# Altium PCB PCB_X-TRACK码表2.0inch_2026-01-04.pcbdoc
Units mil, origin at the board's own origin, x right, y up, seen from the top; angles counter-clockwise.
Board outline 4520 x 5405.38 mil, 2 copper layers (Top Layer, Bottom Layer); 72 components, 59 nets, 273 pads, 238 vias.
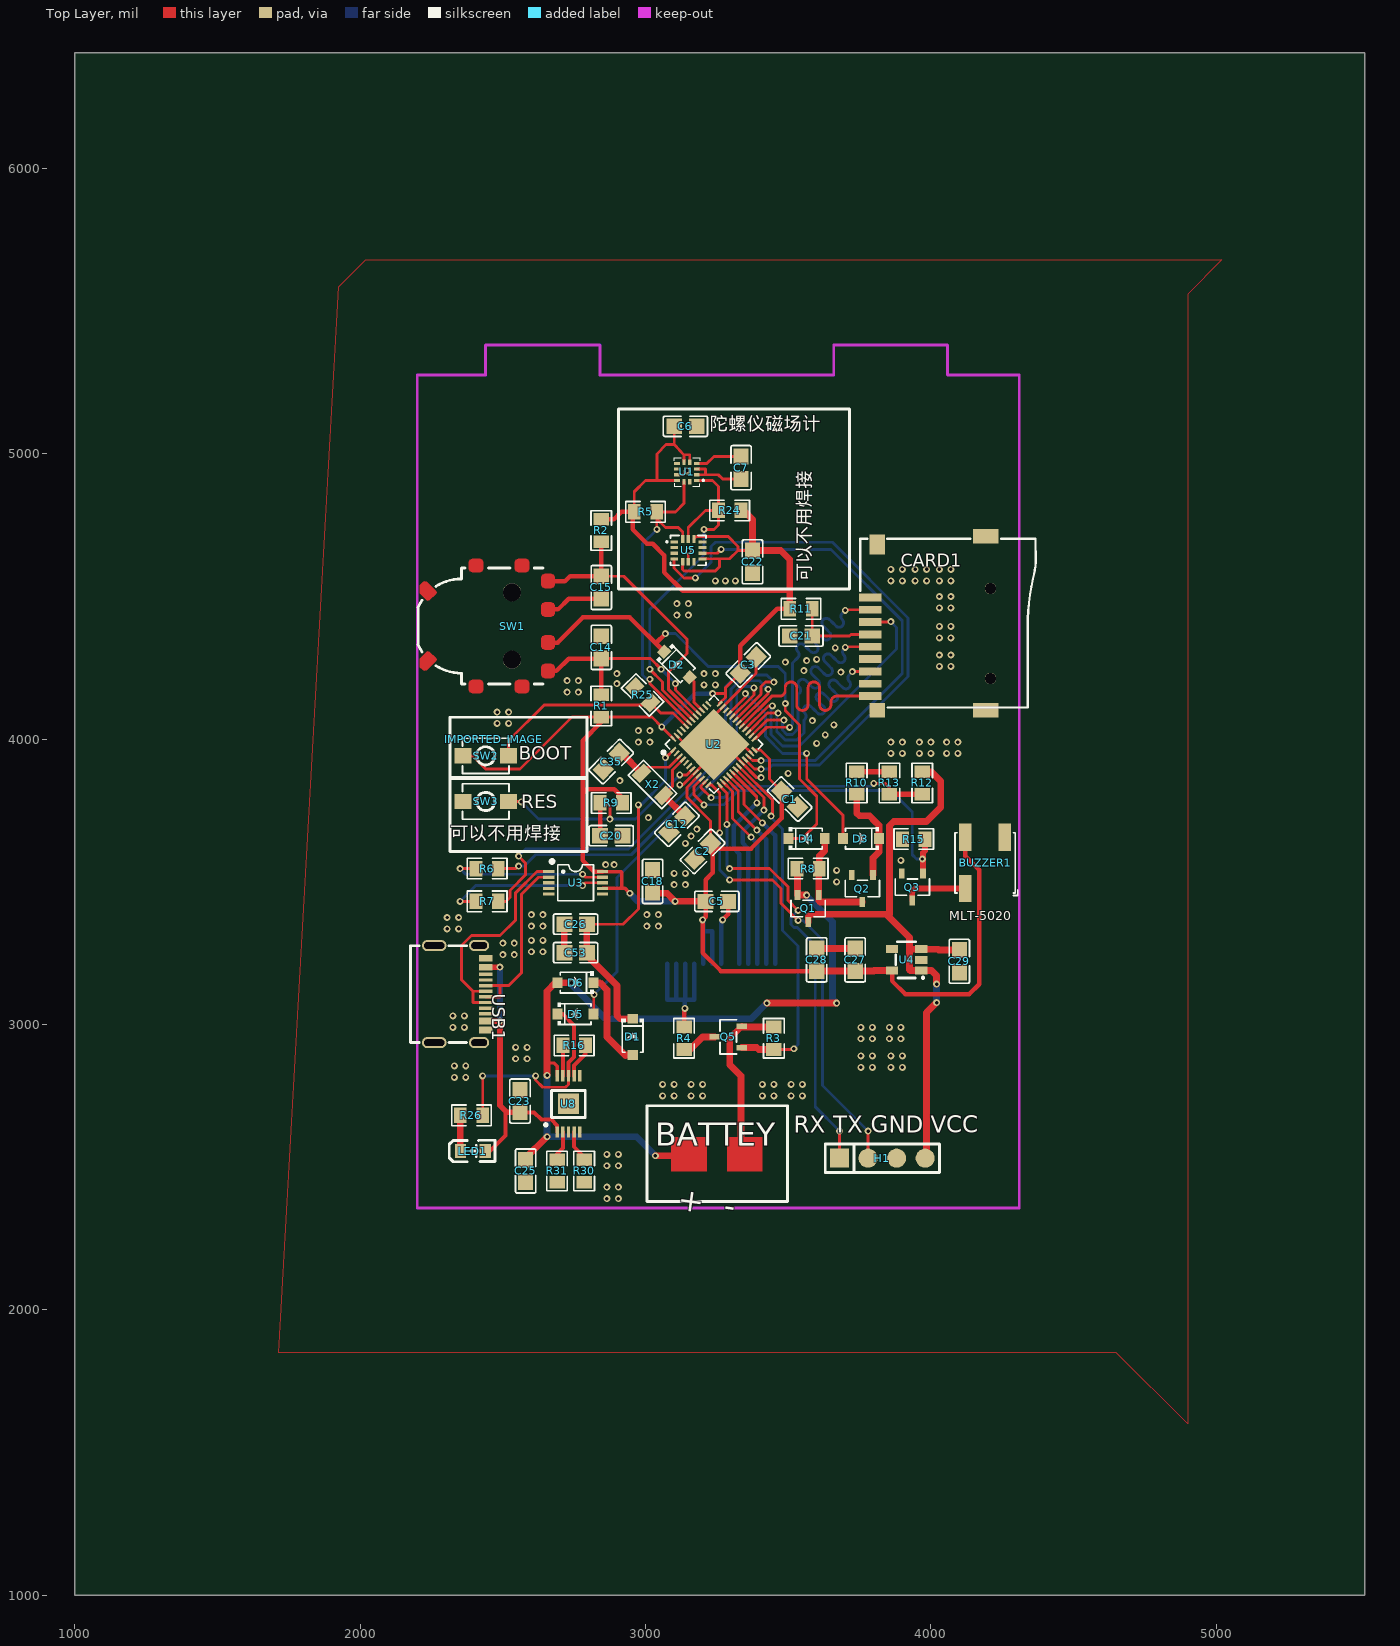
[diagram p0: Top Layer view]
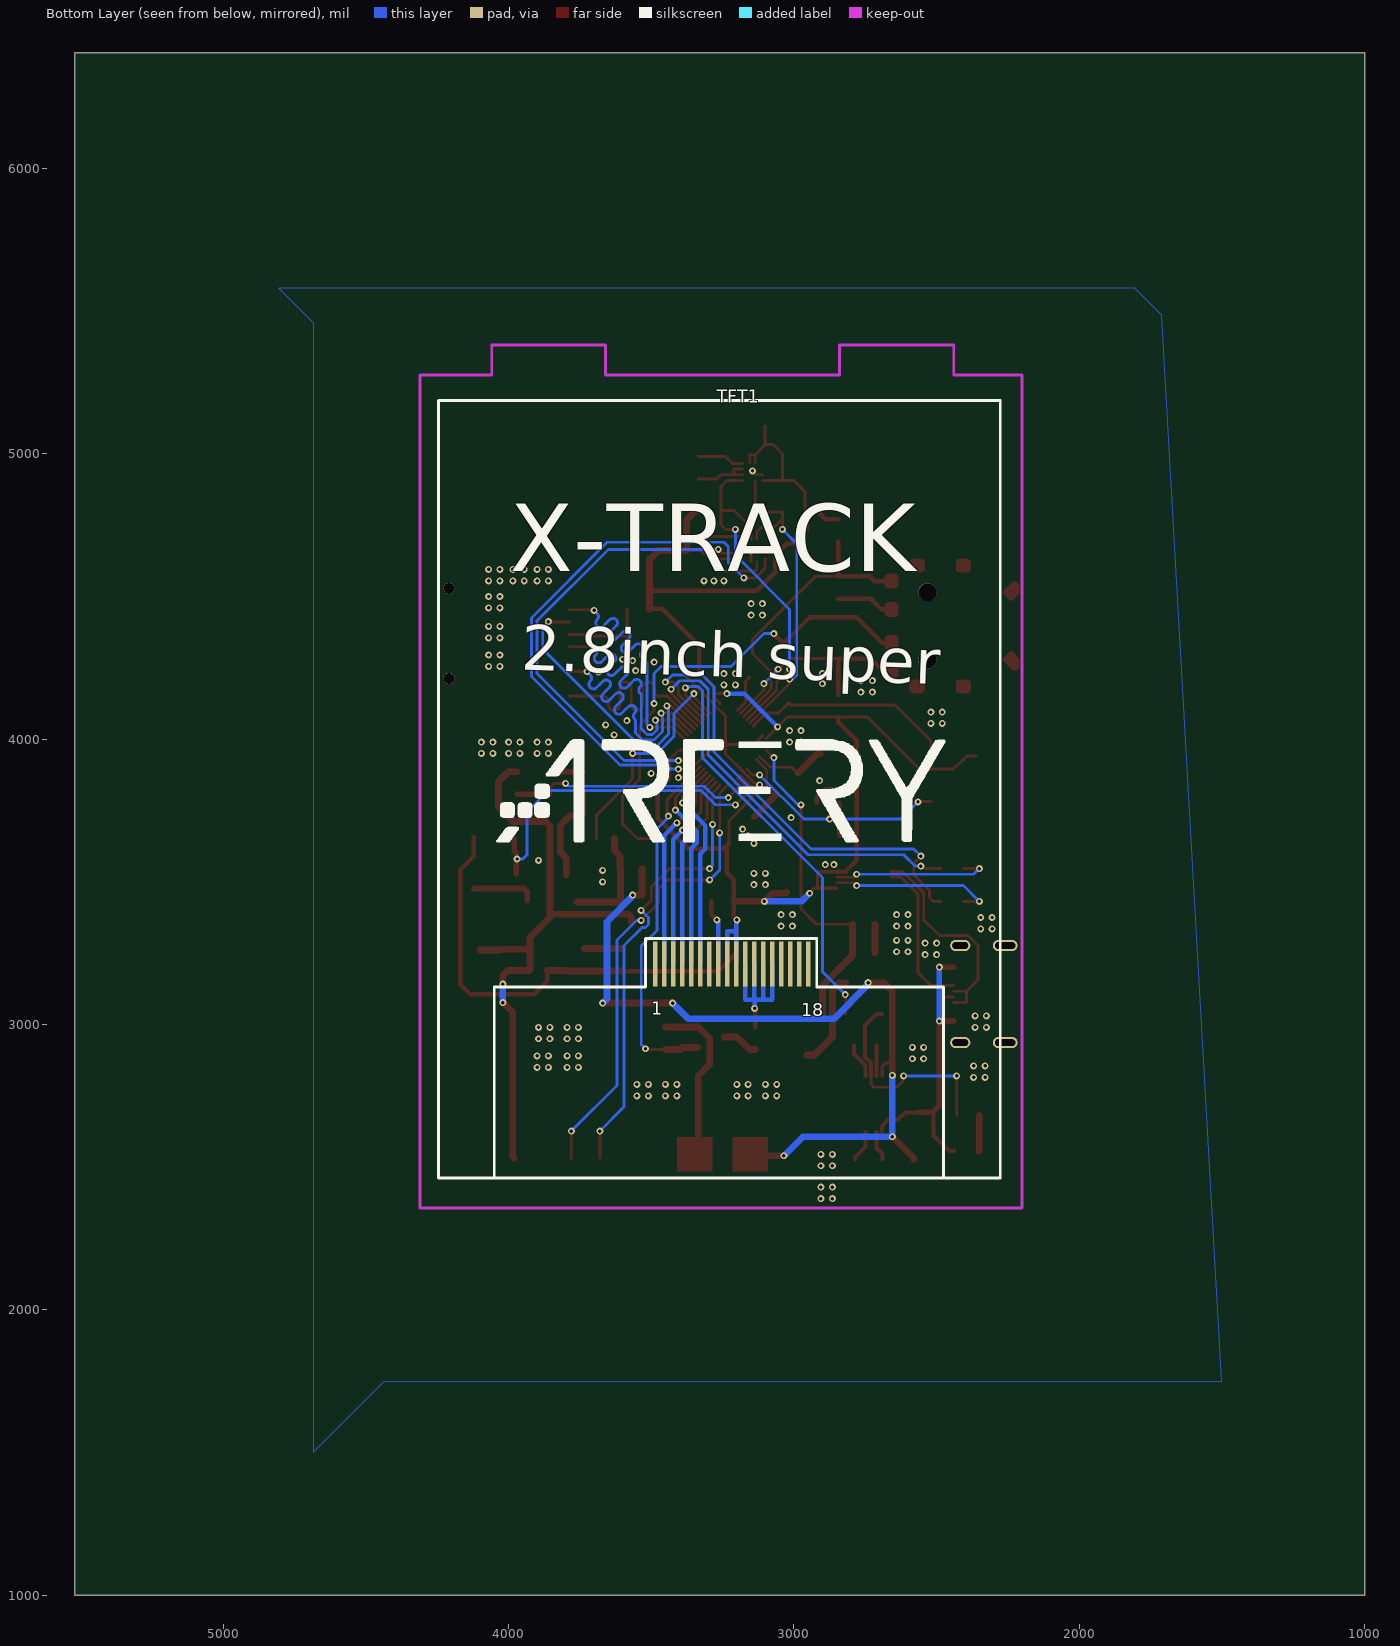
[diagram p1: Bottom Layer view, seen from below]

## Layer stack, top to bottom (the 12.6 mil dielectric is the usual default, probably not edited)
Top Layer: signal copper (thickness not stored)
Dielectric: dielectric 12.6, FR-4, Dk 4.8
Bottom Layer: signal copper (thickness not stored)

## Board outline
5520,1000 1000,1000 1000,6405.38 5520,6405.38

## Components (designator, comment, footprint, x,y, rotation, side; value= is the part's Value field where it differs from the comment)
BUZZER1 "MLT-5020" BUZ-SMD_3P-L5.2-W5.2-P3.50-BR 4190.01,3566.58 r0 top
C1 "100nF" C0805 3505,3790 r135 top
C2 "100nF" C0805 3200.01,3606.58 r45 top
C3 "100nF" C0805 3360,4260 r225 top
C5 "10uF" C0805 3250.01,3431.58 r0 top
C6 "100nF" C0805 3140.01,5096.58 r0 top
C7 "100nF" C0805 3335.01,4951.58 r270 top
C12 "9pF" C0805 3110.01,3701.58 r45 top
C14 "100nF" C0805 2845.01,4321.58 r270 top
C15 "100nF" C0805 2845.01,4531.58 r90 top
C18 "100nF" C0805 3025.01,3501.58 r90 top
C20 "100nF" C0805 2880.01,3661.58 r0 top
C21 "1uF" C0805 3545.01,4361.58 r180 top
C22 "100nF" C0805 3375.01,4621.58 r270 top
C23 "10uF" C0805 2560.01,2731.58 r270 top
C25 "10uF" C0805 2580.01,2486.58 r90 top
C26 "10uF" C0805 2755.01,3351.58 r0 top
C27 "10uF" C0805 3735.01,3226.58 r90 top
C28 "10uF" C0805 3600.01,3226.58 r90 top
C29 "10uF" C0805 4100.01,3221.58 r270 top
C35 "9pF" C0805 2880.01,3921.58 r45 top
C53 "100nF" C0805 2755.01,3251.58 r180 top
CARD1 "TF卡插座-TF-015" TF卡插座-TF-015 3990.01,4406.58 r90 top
D1 "1N4148W_C7420318" SOD-123_L2.7-W1.6-LS3.7-FD 2955.01,2956.58 r90 top
D2 "1N4148W_C7420318" SOD-123_L2.7-W1.6-LS3.7-FD 3110.01,4261.58 r135 top
D3 "1N4148W_C7420318" SOD-123_L2.7-W1.6-LS3.7-FD 3755.01,3651.58 r0 top
D4 "1N4148W_C7420318" SOD-123_L2.7-W1.6-LS3.7-FD 3565.01,3651.58 r180 top
D5 "1N4148W_C7420318" SOD-123_L2.7-W1.6-LS3.7-FD 2755.01,3036.58 r180 top
D6 "1N4148W_C7420318" SOD-123_L2.7-W1.6-LS3.7-FD 2755.01,3146.58 r0 top
H1 "Z-211-0411-0021-001" HDR-TH_4P-P2.54-V-M 3830.01,2531.58 r0 top
IMPORTED_IMAGE "IMPORTED_IMAGE" IMPORTED_IMAGE 2468.91,4000.51 r0 top
LED1 "XL-2012SURC" LED0805-RD_RED 2395.01,2556.58 r0 top
Q1 "SI2305" SOT-23-3_L2.9-W1.3-P1.90-LS2.4-BR 3570.01,3406.58 r90 top
Q2 "SI2302" SOT-23-3_L2.9-W1.3-P1.90-LS2.4-BR 3760.01,3476.58 r90 top
Q3 "SI2302" SOT-23-3_L2.9-W1.3-P1.90-LS2.4-BR 3935.01,3481.58 r90 top
Q5 "SI2302" SOT-23-3_L2.9-W1.3-P1.90-LS2.4-BR 3290.01,2956.58 r0 top
R1 "10K" R0805 2845.01,4116.58 r270 top
R2 "10K" R0805 2845.01,4731.58 r270 top
R3 "10K" R0805 3450.01,2951.58 r90 top
R4 "4R7" R0805 3135.01,2951.58 r270 top
R5 "10K" R0805 3000.01,4796.58 r0 top
R6 "100" R0805 2445.01,3546.58 r0 top
R7 "100" R0805 2445.01,3431.58 r180 top
R8 "20k" R0805 3570.01,3546.58 r0 top
R9 "10K" R0805 2880.01,3776.58 r180 top
R10 "20k" R0805 3740.01,3846.58 r270 top
R11 "4R7" R0805 3545.01,4456.58 r0 top
R12 "20k" R0805 3970.01,3846.58 r90 top
R13 "20k" R0805 3855.01,3846.58 r270 top
R15 "10K" R0805 3940,3650 r0 top
R16 "10K" R0805 2750.01,2926.58 r0 top
R24 "10K" R0805 3295.01,4801.58 r180 top
R25 "10K" R0805 2990,4155 r135 top
R26 "2.2K" R0805 2390.01,2681.58 r0 top
R30 "2k" R0805 2785.01,2486.58 r90 top
R31 "1k" R0805 2690.01,2486.58 r90 top
SW1 "TSIQ-02FVS3" 贴片旋转编码开关_TSIQ-02FVS3 2355.01,4396.58 r90 top
SW2 "3×4×2.5_2脚小龟" SW-SMD_L4.0-W2.9-LS5.0 2440.01,3941.58 r180 top
SW3 "3×4×2.5_2脚小龟" SW-SMD_L4.0-W2.9-LS5.0 2440.01,3781.58 r0 top
TFT1 "2.8寸TFT 18PIN*0.8 焊接  240*320" "2.8寸TFT SPI,18PIN 0.8MM 240*320" 3220.01,3401.58 r0 bottom
U1 "LIS3MDLTR" LGA-12_L2.0-W2.0-P0.50-BL 3145.01,4936.58 r90 top
U2 "AT32F403ACGU7" QFN-48_L6.0-W6.0-P0.40-BL-EP4.2 3240.01,3981.58 r45 top
U3 "CH340E" MSOP-10_L3.0-W3.0-P0.50-LS5.0-BL 2755.01,3496.58 r270 top
U4 "ME6230C33M5G" TSOT-23-5_L2.9-W1.6-P0.95-LS2.8-BR 3915.01,3226.58 r0 top
U5 "LSM6DSMTR" LGA-14_L3.0-W2.5-P0.50-TL 3150.01,4661.58 r0 top
U8 "BQ24092DGQT" HVSSOP-10_L3.0-W3.0-P0.50-LS4.9-BL-EP 2730.01,2721.58 r0 top
USB1 "GT-USB-7010B" USB-C-SMD_GT-USB-7010B 2350.01,3106.58 r270 top
X2 "32.768KHz" OSC-SMD_2P-L3.2-W1.5 3025.01,3841.58 r315 top
? "" ? 3260.01,5757.48 r0 top
? "" ? 4793.21,3876.89 r0 top
? "" ? 2400.58,3824.38 r0 top
? "" ? 3260.76,5059.93 r0 top

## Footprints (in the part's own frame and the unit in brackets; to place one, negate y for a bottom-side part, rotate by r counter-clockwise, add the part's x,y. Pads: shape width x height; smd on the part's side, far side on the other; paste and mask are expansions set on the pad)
"2.8寸TFT SPI,18PIN 0.8MM 240*320" [mil]
BUZ-SMD_3P-L5.2-W5.2-P3.50-BR [mm]
  rect 1.12x2.425 smd paste+0 mask+0.051: 1(1.75,2.287) 2(-1.75,2.287) 3(-1.75,-2.288)
  silkscreen extent -2.68,-2.9 2.9,2.68
C0805 [mm]
  rect 1.41x1.35 smd paste-100 mask+0.051: 1(-1,0) 2(1,0)
  silkscreen extent -1.96,-0.9 1.96,0.9
HDR-TH_4P-P2.54-V-M [mm]
  rect 1.7x1.7 smd paste+0 mask+0.051: 1(-3.81,0)
  round 1.7 smd paste+0 mask+0.051: 2(-1.27,0) 3(1.27,0) 4(3.81,0)
  silkscreen extent -5.08,-1.27 5.08,1.27
HVSSOP-10_L3.0-W3.0-P0.50-LS4.9-BL-EP [mm]
  rect 0.3x1 smd paste+0 mask+0.051: 1(-1,-2.5) 2(-0.5,-2.5) 3(0,-2.5) 4(0.5,-2.5) 5(1,-2.5) 6(1,2.5) 7(0.5,2.5) 8(0,2.5) 9(-0.501,2.5) 10(-1.001,2.5)
  rect 1.89x1.83 smd paste+0 mask+0.051: 11(0,0)
  silkscreen extent -2.13,-1.98 1.5,1.2
IMPORTED_IMAGE [mil]
LED0805-RD_RED [mm]
  rect 1x1.25 smd paste+0 mask+0.051: 1(-1.1,0) 2(1.1,0)
  silkscreen extent -2.1,-0.95 1.98,0.96
LGA-12_L2.0-W2.0-P0.50-BL [mm]
  rect 0.28x0.5 smd paste+0 mask+0.051: 1(-0.75,-0.875) 2(-0.25,-0.875) 3(0.25,-0.875) 4(0.75,-0.875) 7(0.75,0.875) 8(0.25,0.875) 9(-0.25,0.875) 10(-0.75,0.875)
  rect 0.5x0.28 smd paste+0 mask+0.051: 5(0.875,-0.25) 6(0.875,0.25) 11(-0.875,0.25) 12(-0.875,-0.25)
  silkscreen extent -1.27,-1.53 1.27,1.14
LGA-14_L3.0-W2.5-P0.50-TL [mm]
  rect 0.675x0.28 smd paste+0 mask+0.051: 1(-1.262,0.75) 2(-1.262,0.25) 3(-1.262,-0.25) 4(-1.262,-0.75) 8(1.262,-0.75) 9(1.262,-0.25) 10(1.262,0.25) 11(1.262,0.75)
  rect 0.28x0.675 smd paste+0 mask+0.051: 5(-0.5,-1.012) 6(0,-1.012) 7(0.5,-1.012) 12(0.5,1.012) 13(0,1.012) 14(-0.5,1.012)
  silkscreen extent -1.98,-1.33 1.58,1.33
MSOP-10_L3.0-W3.0-P0.50-LS5.0-BL [mm]
  rect 0.28x1 smd paste+0 mask+0.051: 1(-1,-2.4) 2(-0.5,-2.4) 3(0,-2.4) 4(0.5,-2.4) 5(1,-2.4) 6(1,2.4) 7(0.5,2.4) 8(0,2.4) 9(-0.5,2.4) 10(-1,2.4)
  silkscreen extent -2.05,-2.25 1.6,1.6
OSC-SMD_2P-L3.2-W1.5 [mm]
  rect 1x1.5 smd paste+0 mask+0.051: 1(-1.397,0) 2(1.397,0)
  silkscreen extent -2.1,-0.95 2.1,0.95
QFN-48_L6.0-W6.0-P0.40-BL-EP4.2 [mm]
  rect 0.665x0.2 smd paste-100 mask+0.05: 1(-2.908,2.2) 2(-2.908,1.8) 3(-2.908,1.4) 4(-2.908,1) 5(-2.908,0.6) 6(-2.908,0.2) 7(-2.908,-0.2) 8(-2.908,-0.6) 9(-2.908,-1) 10(-2.908,-1.4) 11(-2.908,-1.8) 12(-2.908,-2.2) 25(2.908,-2.2) 26(2.908,-1.8) 27(2.908,-1.4) 28(2.908,-1) 29(2.908,-0.6) 30(2.908,-0.2) 31(2.908,0.2) 32(2.908,0.6) 33(2.908,1) 34(2.908,1.4) 35(2.908,1.8) 36(2.908,2.2)
  rect 0.2x0.665 smd paste-100 mask+0.05: 13(-2.2,-2.908) 14(-1.8,-2.908) 15(-1.4,-2.908) 16(-1,-2.908) 17(-0.6,-2.908) 18(-0.2,-2.908) 19(0.2,-2.908) 20(0.6,-2.908) 21(1,-2.908) 22(1.4,-2.908) 23(1.8,-2.908) 24(2.2,-2.908) 37(2.2,2.908) 38(1.8,2.908) 39(1.4,2.908) 40(1,2.908) 41(0.6,2.908) 42(0.2,2.908) 43(-0.2,2.908) 44(-0.6,2.908) 45(-1,2.908) 46(-1.4,2.908) 47(-1.8,2.908) 48(-2.2,2.908)
  rect 4.5x4.5 smd paste-100: 49(0,0)
  silkscreen extent -3.76,-3.08 3.08,3.08
R0805 [mil]
  rect 44.59x54.21 smd paste-3937.01 mask+2: 1(-39.37,0) 2(39.37,0)
  silkscreen extent -69,-36 69,36
SOD-123_L2.7-W1.6-LS3.7-FD [mm]
  rect 0.88x0.96 smd paste+0 mask+0.051: 1(-1.61,0) 2(1.61,0)
  silkscreen extent -1.38,-1 1.6,1
SOT-23-3_L2.9-W1.3-P1.90-LS2.4-BR [mm]
  rect 0.9x0.5 smd paste+0 mask+0.051: 1(1.2,-0.95) 2(1.2,0.95) 3(-1.2,0)
  silkscreen extent -0.73,-1.53 0.73,1.53
SW-SMD_L4.0-W2.9-LS5.0 [mm]
  rect 1.53x1.36 smd paste+0 mask+0.051: 1(-2.035,0) 2(2.035,0)
  silkscreen extent -2.08,-1.58 2.08,1.58
TF卡插座-TF-015 [mm]
  rect 0.7x2 smd paste+0 mask+0.102: 1(2.292,5.145) 2(1.192,5.143) 3(0.096,5.145) 4(-1.004,5.145) 5(-2.103,5.145) 6(-3.201,5.145) 7(-4.297,5.145) 8(-5.395,5.145) 9(-6.499,5.145)
  rect 1.27x1.397 smd paste+0 mask+0.102: 10(-7.747,4.507)
  rect 1.27x2.286 smd paste+0 mask+0.102: 11(-7.747,-5.145) 12(7.747,-5.145)
  rect 1.778x1.397 smd paste+0 mask+0.102: 13(6.985,4.507)
  round 1 hole 1 unplated paste+0: ""(-4.915,-5.557) ""(3.084,-5.554)
  silkscreen extent -7.52,-9.6 7.52,6.02
TSOT-23-5_L2.9-W1.6-P0.95-LS2.8-BR [mm]
  rect 1.1x0.7 smd paste+0 mask+0.051: 1(1.294,-0.951) 2(1.294,-0.001) 3(1.294,0.951) 4(-1.294,0.951) 5(-1.294,-0.949)
  silkscreen extent -0.97,-1.65 1.52,1.61
USB-C-SMD_GT-USB-7010B [mm]
  rect 0.6x1.2 smd paste-100 mask+0.051: 1(-3.2,2.3) 2(-2.4,2.3) 11(2.4,2.3) 12(3.2,2.3)
  rect 0.3x1.2 smd paste-100 mask+0.051: 3(-1.75,2.3) 4(-1.25,2.3) 5(-0.75,2.3) 6(-0.25,2.3) 7(0.25,2.3) 8(0.75,2.3) 9(1.25,2.3) 10(1.75,2.3)
  oval 1x1.8 hole 0.6 slot 1.4 at 90 deg paste+0 mask+0.051: 13(-4.32,1.7) 14(4.32,1.7)
  oval 1x2.2 hole 0.6 slot 1.8 at 90 deg paste+0 mask+0.051: 15(-4.32,-2.3) 16(4.32,-2.3)
  silkscreen extent -4.3,-4.4 4.3,0.57
贴片旋转编码开关_TSIQ-02FVS3 [mm]
  round 1.6 hole 1.6 unplated paste+0: ""(-3,-4.5) ""(3,-4.5)
  Top Layer region: -6,-1.65 -5.912,-1.862 -5.7,-1.95 -5.1,-1.95 -4.888,-1.862 -4.8,-1.65 -4.8,-0.95 -4.888,-0.738 -5.1,-0.65 -5.7,-0.65 -5.912,-0.738 -6,-0.95
  Top Layer region: -6,-5.75 -5.912,-5.962 -5.7,-6.05 -5.1,-6.05 -4.888,-5.962 -4.8,-5.75 -4.8,-5.05 -4.888,-4.838 -5.1,-4.75 -5.7,-4.75 -5.912,-4.838 -6,-5.05
  Top Layer region: -4.65,-8 -4.562,-8.212 -4.35,-8.3 -3.65,-8.3 -3.438,-8.212 -3.35,-8 -3.35,-7.4 -3.438,-7.188 -3.65,-7.1 -4.35,-7.1 -4.562,-7.188 -4.65,-7.4
  Top Layer region: -2.125,-8 -2.037,-8.212 -1.825,-8.3 -1.125,-8.3 -0.913,-8.212 -0.825,-8 -0.825,-7.4 -0.913,-7.188 -1.125,-7.1 -1.825,-7.1 -2.037,-7.188 -2.125,-7.4
  Top Layer region: 0.825,-8 0.913,-8.212 1.125,-8.3 1.825,-8.3 2.037,-8.212 2.125,-8 2.125,-7.4 2.037,-7.188 1.825,-7.1 1.125,-7.1 0.913,-7.188 0.825,-7.4
  Top Layer region: 3.35,-8 3.438,-8.212 3.65,-8.3 4.35,-8.3 4.562,-8.212 4.65,-8 4.65,-7.4 4.562,-7.188 4.35,-7.1 3.65,-7.1 3.438,-7.188 3.35,-7.4
  Top Layer region: 4.8,-5.75 4.888,-5.962 5.1,-6.05 5.7,-6.05 5.912,-5.962 6,-5.75 6,-5.05 5.912,-4.838 5.7,-4.75 5.1,-4.75 4.888,-4.838 4.8,-5.05
  Top Layer region: 4.8,-1.65 4.888,-1.862 5.1,-1.95 5.7,-1.95 5.912,-1.862 6,-1.65 6,-0.95 5.912,-0.738 5.7,-0.65 5.1,-0.65 4.888,-0.738 4.8,-0.95
  Top Layer region: 2.3,2.85 2.25,3 2.3,3.1 2.9,3.7 3.65,3.7 3.95,3.4 4,3.25 3.95,3.1 3.1,2.25 3,2.2 2.85,2.25
  Top Layer region: -2.3,2.85 -2.25,3 -2.3,3.1 -2.9,3.7 -3.65,3.7 -3.95,3.4 -4,3.25 -3.95,3.1 -3.1,2.25 -2.95,2.2 -2.85,2.25
  silkscreen extent -5.15,-7.25 5.15,3.86
? [mil]

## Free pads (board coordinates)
  rect 15.75x157.48 smd far side paste+0 mask+3.94: 1(3485.45,3212.6) 2(3453.95,3212.6) 3(3422.45,3212.6) 4(3390.96,3212.6) 5(3359.46,3212.6) 6(3327.97,3212.6) 7(3296.47,3212.6) 8(3264.97,3212.6) 9(3233.48,3212.6) 10(3201.98,3212.6) 11(3170.49,3212.6) 12(3138.99,3212.6) 13(3107.49,3212.6) 14(3076,3212.6) 15(3044.5,3212.6) 16(3013.01,3212.6) 17(2981.51,3212.6) 18(2950.01,3212.6)

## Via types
v1: diameter 24.41, hole 12.2, Top Layer to Bottom Layer, tented both sides, 238 vias

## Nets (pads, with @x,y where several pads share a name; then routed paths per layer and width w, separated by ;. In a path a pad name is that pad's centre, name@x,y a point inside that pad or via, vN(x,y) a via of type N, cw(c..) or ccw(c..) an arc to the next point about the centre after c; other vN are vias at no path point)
3V3_MCU: BUZZER1.2 C1.2 C2.2 C3.2 C5.1 C6.1 C18.1 C22.1 C27.1 C28.1 pad.9 pad.10 R1.2 R2.1 R5.1 R9.1 R11.1 R24.1 SW2.2 U1.5 U1.6 U1.10 U2.9 U2.24 U2.36 U2.48 U3.7 U3.10 U4.5 U5.5 U5.8 U5.12 | length 8667.1
  Top Layer w10: SW2.2 2393.42,3941.58 2440,3895 2560,3895 2742.21,4077.21 R1.2 3022.81,4077.18 v1(3056.9,4042.68) U2.48 ; U5.5 3130.01,4594.98 3135.01,4589.98 3245.01,4589.98 3259.51,4604.48 3259.51,4632.08 ; U5.12 3178.26,4710 3290,4710 3324.41,4675.59 3324.41,4660.98
  Top Layer w10.04: R5.1 2960.64,4867.21 3000.48,4907.05 U1.10@3110.56,4907.05 ; 3038.94,4907.05 3040,4908.11 3040,5000 3072.18,5032.18 3100.61,5032.18 ; C6.1 3100.61,5032.18 ; U1.6@3135.21,4971.08 3135.21,4996.38 3100.61,5032.18 ; 3135.21,4996.58 3154.85,4996.58 U1.5@3154.85,4971.03 ; U2.9 3145.01,3830.9 3145.01,3796.58 3227.85,3713.74 C2.2 ; U5.8 3294.51,4632.08 3324.41,4660.98 C22.1 ; U2.36 3259.71,4126.28 3280.01,4146.58 3280.01,4180.01 C3.2 ; U2.24 3403.11,3961.88 3435.01,3929.98 3435.01,3859.98 C1.2@3477.11,3817.88
  Top Layer w11.81: U3.7 2928.11,3476.89 v1(2945,3460) ; U3.10 2915.01,3534.98 2917.01,3532.98 2917.01,3476.88 ; v1(3235,4160) 3280.01,4159.08
  Top Layer w15.75: R1.2 2845.01,4059.98 2780.01,3994.98 2780.01,3809.98 ; R2.1 2889.38,4770.95 2915.01,4796.58 R5.1 ; U3.10 2819.01,3535.98 2780.01,3574.98 2780.01,3809.98 ; R9.1 2919.41,3795.58 2890.01,3824.98 2795.01,3824.98 2780.01,3809.98 ; R5.1 2955.01,4790.98 2955.01,4734.98 3005.01,4684.98 3025.01,4684.98 3065.01,4644.98 3065.01,4584.98 3130.01,4520.28 3505.61,4520.28 ; C5.1 3210.61,3507.18 3235.01,3531.58 3235.01,3627.28 C2.2 3245.71,3616.58 3370.01,3616.58 3477.11,3723.68 C1.2@3477.11,3817.88 ; C5.1 3210.64,3377.21 v1(3200.01,3366.58) 3200.01,3251.58 3264.38,3187.21 C28.1 ; C3.2@3332.11,4232.18 3332.11,4327.18 3461.61,4456.58 R11.1 ; U4.5 3864.07,3152.52 3910.01,3106.58 4135.01,3106.58 4170.01,3141.58 4170.01,3541.58 4121.11,3590.48 BUZZER1.2
  Top Layer w23.62: C18.1 3027.22,3460 3075,3460 v1(3103.42,3431.58) C5.1 ; R24.1 3343.42,4801.58 3375.01,4769.99 C22.1 3474.05,4660.95 3505.64,4629.36 R11.1 ; C28.1 C27.1 3800.01,3187.21 3802.02,3189.22 U4.5
  Bottom Layer w15.75: v1(3056.9,4042.68) 3174.22,4160 v1(3235,4160) ; v1(3200.01,3366.58) 3201.98,3364.61 pad.10 ; 3201.98,3326.58 3233.48,3326.58 pad.9
  Bottom Layer w23.62: v1(2945,3460) 2973.42,3431.58 v1(3103.42,3431.58)
5V0_USB: C23.2 LED1.2 U8.1 USB1.2 USB1.11 | length 1010.9
  Top Layer w13.78: LED1.2 2455.01,2556.58 2510.01,2611.58 2510.01,2692.21 ; C23.2 2609.41,2692.18 2635.01,2666.58 2670.01,2666.58 2690.01,2646.58 U8.1
  Top Layer w19.68: USB1.11 v1(2490.01,3012.09) 2490.01,2716.58 2514.38,2692.21 C23.2 ; USB1.2 v1(2490.01,3201.07)
  Bottom Layer w19.68: v1(2490.01,3012.09) v1(2490.01,3201.07)
BAT_CHG_DET: D5.1 U2.32 | length 1541.6
  Top Layer w10: D5.1 2818.4,3103.4 v1(2820,3105) ; U2.32 3380,4154.97 v1(3380,4180)
  Bottom Layer w10: v1(2820,3105) 2900,3185 2900,3515 3320,3935 3320,4170 3335,4185 3375,4185 v1(3380,4180)
BAT_DET: R12.1 R13.2 U2.11 | length 865.6
  Top Layer w10: U2.11 3195,3836.34 3195,3830 v1(3230,3795) ; v1(3800,3845) 3840,3845 3855.01,3829.99 R13.2
  Top Layer w19.68: R13.2 R12.1
  Bottom Layer w10: v1(3230,3795) 3275,3795 3315,3835 3790,3835 v1(3800,3845)
BOOT0: R25.1 SW2.1 U2.44 | length 764.2
  Top Layer w10: SW2.1 2520.13,3995.13 2645,4120 3010.68,4120 R25.1 3053.42,4091.58 3096.61,4091.58 U2.44
BUZZ: Q3.1 R15.2 U2.10 | length 1214.7
  Top Layer w10: U2.10 3170,3833.62 3170,3805 v1(3205,3770)
  Top Layer w19.68: Q3.1 3972.41,3601.58 3979.37,3608.54 R15.2
  Bottom Layer w10: v1(3205,3770) 3275,3770 3324.81,3819.81 3860.19,3819.81 3935,3745 3935,3595 3950,3580 v1(3970,3580)
BUZZER1_3: BUZZER1.3 Q3.3 | length 222.3
  Top Layer w19.68: Q3.3@3935.01,3434.38 3935.01,3466.58 3945.11,3476.48 BUZZER1.3
C12_2: C12.2 U2.4 X2.2 | length 257.8
  Top Layer w10: X2.2 3095.01,3833.8 3095.01,3892.26 U2.4
  Top Layer w23.62: X2.2 C12.2
C35_2: C35.2 U2.3 X2.1 | length 265.3
  Top Layer w10: X2.1 3007.23,3901.58 3082.06,3901.58 U2.3
  Top Layer w23.62: C35.2 2917.17,3949.42 X2.1
CARD1_4: C21.1 CARD1.4 R11.2 | length 300.3
  Top Layer w10.04: R11.2 C21.1 3715.01,4361.58 3720.48,4367.05 CARD1.4@3787.45,4367.05
D1_1: D1.1 D6.2 | length 339.6
  Top Layer w23.62: D6.2 2840.01,3146.58 2865.01,3121.58 2865.01,2956.58 2930.01,2891.58 2931.62,2893.19 D1.1
D3_2: D3.2 Q2.1 R10.2 | length 481.5
  Top Layer w19.68: Q2.1 3797.41,3583.98 3818.4,3604.97 D3.2
  Top Layer w23.62: R10.2 3740.01,3741.58 3750.01,3731.58 3785.01,3731.58 3805.01,3711.58 3818.4,3698.19 D3.2 3818.4,3604.97 3797.41,3583.98 Q2.1
D4_1: D4.1 Q1.1 Q2.3 R8.2 | length 652.3
  Top Layer w19.68: Q1.1 3607.41,3434.18 3615.01,3426.58 3760.01,3426.58 Q2.3@3760.01,3429.38 ; Q1.1 3609.38,3455.8 R8.2
  Top Layer w23.62: Q1.1 3607.41,3434.18 3612.21,3429.38 Q2.3@3760.01,3429.38 ; Q1.1 3607.41,3544.61 R8.2 3609.38,3590.95 3628.4,3609.97 D4.1
D5_2: D5.2 R26.2 U8.8 | length 758.3
  Top Layer w10.04: R26.2 v1(2429.38,2820) ; v1(2615.01,2819.98) 2615.01,2804.98 2640.01,2779.98 2720.01,2779.98 2730.01,2789.98 U8.8
  Top Layer w13.78: D5.2 2710.01,3036.58 2750.01,2996.58 2750.01,2886.58 2730,2866.57 U8.8
  Bottom Layer w10.04: v1(2429.38,2820) v1(2615.01,2819.98)
EC_A: C14.2 R1.1 U2.40 | length 765.6
  Top Layer w10: C14.2 3017.79,4282.21 v1(3055,4245) ; v1(3105,4195) 3105,4172.27 U2.40
  Top Layer w15.75: 2658.16,4239.1 2687.53,4239.1 2730.64,4282.21 C14.2 R1.1
  Bottom Layer w10: v1(3055,4245) v1(3105,4195)
EC_B: C15.2 R2.2 U2.41 | length 1043.7
  Top Layer w10: C15.2 2924.05,4570.95 3145,4350 3145,4300 3080,4235 3080,4174.99 U2.41
  Top Layer w15.75: 2658.11,4554.08 2717.51,4554.08 2735.61,4570.98 C15.2 ; C15.2 R2.2
EC_KEY: D2.2 D4.2 | length 1712.1
  Top Layer w10: v1(3490,4125) 3490.01,4099.98 3540.01,4049.98 3540.01,3859.98 3600.01,3799.98 3600.01,3703.18 3548.41,3651.58 D4.2
  Top Layer w15.75: 2658.16,4338.51 2691.94,4338.51 2780.01,4426.58 2945.01,4426.58 D2.2 ; 3036.3,4335.29 3036.3,4336.3 v1(3070,4370)
  Bottom Layer w10: v1(3070,4370) 3105,4370 3220,4255 3465,4255 3490,4230 v1(3490,4125)
EC_KEY_DET: D2.1 U2.39 | length 133.2
  Top Layer w10: D2.1 3170.01,4201.58 3170.01,4129.53 U2.39
GND: BUZZER1.1 C1.1 C2.1 C3.1 C5.2 C6.2 C7.2 C12.1 C14.1 C15.1 C18.2 C20.2 C21.2 C22.2 C23.1 C25.1 C26.1 C27.2 C28.2 C29.2 C35.1 C53.2 CARD1.6 CARD1.10 CARD1.11 CARD1.12 CARD1.13 H1.3 pad.1 pad.8 Q2.2 Q3.2 Q5.2 R3.2 R10.1 R13.1 R15.1 R16.2 R25.2 R30.1 R31.1 SW3.1 U1.2 U1.3 U1.9 U1.12 U2.8 U2.20 U2.23 U2.35 U2.47 U2.49 U3.3 U4.2 U5.1 U5.2 U5.3 U5.6 U5.7 U8.3 U8.7 U8.11 USB1.1 USB1.12 USB1.13 USB1.14 USB1.15 USB1.16 | length 2867.9
  Top Layer w10: U2.47 3139.79,3981.58 U2.49 ; U1.9 3131.74,4926.74 v1(3145,4940) ; v1(3120,3840) 3131.83,3840 U2.8 3240.01,3948.18 U2.49 ; U5.6 v1(3150,4660) ; U2.23@3371.07,3950.75 3340.24,3981.58 U2.49 ; C3.1 3387.84,4229.63 U2.35 3240.01,4081.8 U2.49 ; v1(3405,3865) 3389.99,3865 U2.20 3273.41,3981.58 U2.49
  Top Layer w10.04: U1.2@3179.41,4926.78 3209.81,4926.78 ; U1.3@3179.41,4946.38 3210.01,4946.38 3209.81,4926.78 ; C7.2 3270.61,4912.18 3254.81,4926.78 3209.81,4926.78
  Top Layer w13.78: U8.7 2749.69,2856.58 2789.38,2896.27 R16.2
  Top Layer w15.75: 2658.16,4454.65 2693.08,4454.65 2730.64,4492.21 C15.1 ; v1(3270.01,3366.58) 3289.38,3385.95 C5.2
  Top Layer w19.68: R10.1 R13.1
  Top Layer w23.62: C53.2 C26.1 ; 3335.01,2534.98 3335.01,2819.98 3295.01,2859.98 3295.01,2951.68 Q5.2@3337.21,2993.98 ; Q5.2@3337.25,2993.98 3340.28,2990.95 R3.2 ; C28.2 C27.2
  Bottom Layer w15.75: pad.8 3264.97,3361.54 v1(3270.01,3366.58)
  other v1: 2865,2390 2905,2390 2865,2430 2905,2430 2865,2505 2905,2505 2865,2545 2905,2545 3060,2750 3100,2750 3160,2750 3200,2750 3410,2750 3450,2750 3510,2750 3550,2750 3060,2790 3100,2790 3160,2790 3200,2790 3410,2790 3450,2790 3510,2790 3550,2790 2330,2815 2370,2815 3755,2850 3795,2850 3860,2850 3900,2850 2330,2855 2370,2855 2545,2880 2585,2880 3755,2890 3795,2890 3860,2890 3900,2890 2545,2920 2585,2920 3755,2950 3795,2950 3855,2950 3895,2950 2325,2990 2365,2990 3755,2990 3795,2990 3855,2990 3895,2990 2325,3030 2365,3030 2500,3245 2540,3245 2600,3255 2640,3255 2500,3285 2540,3285 2600,3295 2640,3295 2305,3335 2345,3335 2600,3345 2640,3345 3005,3345 3045,3345 2305,3375 2345,3375 2600,3385 2640,3385 3005,3385 3045,3385 3100,3490 3140,3490 3670,3500 3100,3530 3140,3530 3670,3540 2860,3560 2890,3560 3895,3575 3140,3635 3160,3660 3180,3685 3010,3725 2910,3855 3500,3880 3860,3950 3900,3950 3960,3950 4000,3950 4055,3950 4095,3950 3600,3985 2975,3990 3015,3990 3860,3990 3900,3990 3960,3990 4000,3990 4055,3990 4095,3990 3630,4015 2975,4030 3015,4030 3660,4050 2480,4055 2520,4055 3585,4065 2480,4095 2520,4095 2725,4165 2765,4165 3205,4190 3245,4190 2900,4195 2725,4205 2765,4205 2900,4230 3205,4230 3245,4230 3685,4235 3555,4240 4030,4255 4070,4255 3490,4270 3565,4275 3600,4280 4030,4295 4070,4295 3665,4320 4030,4355 4070,4355 4030,4395 4070,4395 3110,4435 3150,4435 4030,4460 4070,4460 3110,4475 3150,4475 4030,4500 4070,4500 3245,4555 3280,4555 3315,4555 3860,4555 3900,4555 3945,4555 3985,4555 4030,4555 4070,4555 3860,4595 3900,4595 3945,4595 3985,4595 4030,4595 4070,4595
GPS_RX: H1.1 U2.13 | length 1598.5
  Top Layer w10.04: U2.13 3259.71,3836.88 3285.01,3811.58 v1(3285.01,3701.58) v1@3280.01,3696.58 ; v1(3295.01,3546.58) 3435.01,3546.58 3500.01,3481.58 3500.01,3434.99 v1(3535,3400) ; H1.1 v1(3680.01,2626.58)
  Bottom Layer w10.04: v1(3285.01,3701.58) 3285.01,3556.58 v1(3295.01,3546.58) ; v1(3535,3400) 3510.01,3374.98 3510.01,3349.98 3520.01,3339.98 3531.61,3339.98 3595.01,3276.58 3595.01,2711.58 v1(3680.01,2626.58)
GPS_TX: H1.2 U2.12 | length 1644.2
  Top Layer w10.04: U2.12 3232.2,3839.39 3260.01,3811.58 v1(3260.01,3671.58) ; v1(3295.01,3506.58) 3445.01,3506.58 3475.01,3476.58 3475.01,3424.99 v1(3535,3365) ; H1.2 v1(3780.01,2626.58)
  Bottom Layer w10.04: v1(3260.01,3671.58) 3260.01,3541.58 v1(3295.01,3506.58) ; v1(3535,3365) 3551.59,3365 3620.01,3296.58 3620.01,2786.58 v1(3780.01,2626.58)
IMU_INT1: U2.21 U5.4 | length 1984.9
  Top Layer w10: U5.4 3100.32,4599.68 3135,4565 v1(3175,4565) ; U2.21 3382.27,3895 v1(3405,3895)
  Bottom Layer w10: v1(3175,4565) 3230,4620 3230,4675 3245,4690 3655,4690 3920,4425 3920,4220 3609.79,3909.79 3444.79,3909.79 3430,3895 v1(3405,3895)
IMU_INT2: U2.22 U5.9 | length 1666.8
  Top Layer w10: U5.9 3251.74,4651.74 v1(3265,4665) ; U2.22 3374.54,3925 v1(3405,3925)
  Bottom Layer w10: v1(3265,4665) 3650,4665 3900,4415 3900,4230 3594.98,3924.98 3435.01,3924.98 v1(3405,3925)
LED1_1: LED1.1 R26.1 | length 125.4
  Top Layer w23.62: R26.1 2350.64,2557.64 LED1.1
MCU_RX: R7.1 U2.31 | length 1752.7
  Top Layer w10: R7.1 2511.61,3431.58 2525.01,3444.98 2525.01,3469.98 2580.01,3524.98 2580.01,3564.98 v1(2555,3590) ; U2.31 3405,4157.7 3405,4185 ; 3405,4164.98 3405,4185 ; v1(3450,4200) 3420,4200 3405,4185
  Bottom Layer w10: v1(2555,3590) 2580.01,3614.98 2940.01,3614.98 3280.01,3954.98 3280.01,4184.98 3320.01,4224.98 3425.01,4224.98 v1(3450,4200)
MCU_SCL: R24.2 U1.1 U2.42 U5.13 | length 1255.6
  Top Layer w10: v1(3015,4245) 3060,4200 3060,4172.72 U2.42 ; v1(3205,4735) 3240,4735 3255.64,4750.64 R24.2
  Top Layer w10.04: U5.13 3150.01,4741.58 3210.01,4801.58 R24.2 3255.64,4885.95 3234.54,4907.05 U1.1@3179.46,4907.05
  Bottom Layer w10: v1(3015,4245) 3015,4455 3205,4645 v1(3205,4735)
MCU_SDA: R5.2 U1.11 U2.43 U5.14 | length 1177
  Top Layer w10: v1(3015,4210) 3015,4195.46 U2.43 ; R5.2 3039.38,4735.62 v1(3040,4735)
  Top Layer w10.04: U5.14 3130.33,4726.26 3115.01,4741.58 3070.01,4741.58 3039.38,4772.21 R5.2 3105.01,4796.58 3135.17,4826.74 U1.11
  Bottom Layer w10: v1(3015,4210) 3005,4210 2990,4225 2990,4685 v1(3040,4735)
MCU_TX: R6.2 U2.30 | length 1526.4
  Top Layer w10: R6.2 2546.6,3546.58 v1(2555,3554.98) ; U2.30 3430,4160.44 v1(3430,4175)
  Bottom Layer w10: v1(2555,3554.98) 2575.01,3554.98 2615.01,3594.98 2950.01,3594.98 3300.01,3944.98 3300.01,4174.98 3330.01,4204.98 3400.01,4204.98 v1(3430,4175)
PWR_EN: D3.1 U2.33 | length 792.9
  Top Layer w10: U2.33 3350,4147.25 v1(3350,4160) ; v1(3565,3950) 3565,3860 3691.62,3733.38 D3.1
  Bottom Layer w10: v1(3350,4160) 3420,4090 3420,4010 3480,3950 v1(3565,3950)
R4_2: Q5.3 R4.2 | length 126.1
  Top Layer w23.62: R4.2 3155.64,2912.21 3200.01,2956.58 Q5.3
R16_1: R16.1 U8.9 | length 106.6
  Top Layer w13.78: U8.9 R16.1
RST: C20.1 R9.2 SW3.2 U2.7 | length 941.7
  Top Layer w10: SW3.2 2563.42,3781.58 v1(2565,3780) ; R9.2 2863.42,3776.58 2875,3765 v1(2875,3720) ; v1(3120,3875) 3144.56,3875 U2.7
  Top Layer w15.75: C20.1 R9.2
  Bottom Layer w10: v1(2565,3780) 2625,3720 v1(2875,3720) 2965.01,3719.98 v1(3120,3875)
S$147: 
S$156: 
S$27874: 
S$27878: 
S$27882: 
SCR_BLK: Q5.1 R3.1 U2.19 | length 1274.7
  Top Layer w10: U2.19 3445.01,3787.68 3445.01,3734.98 v1(3440,3730) ; R3.1 3517.24,2912.21 v1(3520.01,2914.98)
  Top Layer w23.62: Q5.1@3337.25,2919.18 3390.01,2919.18 3396.98,2912.21 R3.1
  Bottom Layer w10: v1(3440,3730) 3440.01,3724.98 3480.01,3684.98 3480.01,3329.98 3535.01,3274.98 3535.01,2929.98 v1(3520.01,2914.98)
SCR_CS: pad.5 U2.18 | length 762.9
  Top Layer w10.04: U2.18 3415.01,3795.45 v1(3415.01,3751.58)
  Bottom Layer w15.75: pad.5 3359.46,3617.13 3340.01,3636.58 3340.01,3676.58 v1(3415.01,3751.58)
SCR_DC: pad.4 U2.14 | length 687.7
  Top Layer w10.04: U2.14 3305.01,3816.35 3305.01,3721.58 v1(3370.01,3656.58)
  Bottom Layer w15.75: v1(3370.01,3656.58) 3390.96,3635.63 pad.4
SCR_LEDK: pad.11 pad.12 pad.13 pad.14 R4.1 | length 694.6
  Top Layer w15.75: R4.1 3135.01,3053.84 v1(3137.75,3056.58)
  Bottom Layer w15.75: pad.14 3076.01,3086.58 3170.51,3087.08 pad.11 ; 3107.49,3086.76 pad.13 ; v1(3137.75,3056.58) 3137.75,3086.91 ; 3138.99,3086.91 pad.12
SCR_RES: pad.2 U2.16 | length 726.8
  Top Layer w10.04: U2.16 3345.01,3820.9 3345.01,3771.58 v1(3410.01,3706.58)
  Bottom Layer w15.75: v1(3410.01,3706.58) 3453.95,3662.64 pad.2
SCR_SCL: pad.3 U2.15 | length 707.2
  Top Layer w10.04: U2.15 3325.01,3818.63 3325.01,3746.58 v1(3390.01,3681.58)
  Bottom Layer w15.75: v1(3390.01,3681.58) 3422.45,3649.14 pad.3@3422.45,3212.6
SCR_SDA: pad.6 U2.17 | length 747.4
  Top Layer w10.04: U2.17 3390.01,3798.18 v1(3390.01,3776.58)
  Bottom Layer w15.75: pad.6 3327.97,3598.62 3310.01,3616.58 3310.01,3696.58 v1(3390.01,3776.58)
SD_CD: CARD1.9 U2.29 | length 807.4
  Top Layer w10: U2.29@3337.61,4045.78 3442.51,4150.68 3469.87,4150.68 ccw(c3469.87,4170.68) 3489.87,4170.68 3489.87,4180.68 cw(c3509.87,4180.68) 3529.87,4180.68 3529.87,4150.68 3529.87,4120.68 ccw(c3549.87,4120.68) 3569.87,4120.68 3569.87,4150.68 3569.87,4180.68 cw(c3589.87,4180.68) 3609.87,4180.68 3609.87,4150.68 3609.87,4120.68 ccw(c3629.87,4120.68) 3649.87,4120.68 3649.87,4130.68 cw(c3669.87,4130.68) 3669.87,4150.68 CARD1.9
SD_CS: CARD1.2 U2.25 | length 1001.7
  Top Layer w10: U2.25 3384.71,4001.28 3425.01,4041.58 v1(3505.01,4041.58) ; v1(3700.01,4451.58) 3701.94,4453.51 CARD1.2
  Bottom Layer w10: v1(3505.01,4041.58) 3515.01,4051.58 3515.01,4266.58 3533.72,4285.29 ccw(c3522.59,4296.43) 3533.72,4307.56 cw(c3544.88,4318.68) 3556,4329.84 3567.13,4318.7 3578.27,4307.56 ccw(c3589.4,4318.7) 3600.54,4329.84 3589.4,4340.97 3578.27,4352.11 cw(c3589.4,4363.24) 3600.54,4374.38 3611.67,4363.24 3622.81,4352.11 ccw(c3633.92,4363.26) 3645.08,4374.38 3633.94,4385.51 3622.81,4396.65 cw(c3633.96,4407.77) 3645.08,4418.92 3656.22,4407.79 3667.35,4396.65 ccw(c3678.47,4407.81) 3689.62,4418.92 cw(c3700.76,4430.06) 3689.62,4441.19 v1(3700.01,4451.58)
SD_MISO: CARD1.7 U2.27 | length 948.9
  Top Layer w10: U2.27@3359.93,4023.55 3427.96,4091.58 v1(3465.01,4091.58) ; v1(3725.01,4236.58) CARD1.7
  Bottom Layer w10: v1(3465.01,4091.58) 3460.01,4086.58 3460.01,4026.58 3490.01,3996.58 3530.01,3996.58 3555.01,4021.58 3555.01,4066.58 3557.87,4069.44 ccw(c3546.73,4080.57) 3557.87,4091.71 cw(c3569.02,4102.83) 3580.14,4113.98 3591.28,4102.85 3602.41,4091.71 ccw(c3613.53,4102.87) 3624.68,4113.98 3613.55,4125.12 3602.41,4136.25 cw(c3613.57,4147.37) 3624.68,4158.52 3635.82,4147.39 3646.95,4136.25 ccw(c3658.07,4147.41) 3669.22,4158.52 3658.09,4169.66 3646.95,4180.79 cw(c3658.11,4191.91) 3669.22,4203.06 3680.36,4191.93 3691.49,4180.79 ccw(c3702.61,4191.95) 3713.77,4203.07 cw(c3724.9,4214.2) 3713.77,4225.34 v1(3725.01,4236.58)
SD_MOSI: CARD1.3 U2.28 | length 1006
  Top Layer w10: U2.28 3430.69,4116.58 v1(3445.01,4116.58) ; CARD1.3 3858.77,4410.34 v1(3860.01,4411.58)
  Bottom Layer w10: v1(3445.01,4116.58) 3440.01,4111.58 3440.01,4016.58 3480.01,3976.58 3540.01,3976.58 3880.01,4316.58 3880.01,4391.58 v1(3860.01,4411.58)
SD_SCK: CARD1.5 U2.26 | length 967.7
  Top Layer w10: U2.26 3425.23,4066.58 v1(3485.01,4066.58) ; v1(3700.01,4321.58) 3702.23,4323.8 CARD1.5
  Bottom Layer w10: v1(3485.01,4066.58) 3480.01,4061.58 3480.01,4031.58 3495.01,4016.58 3515.01,4016.58 3535.01,4036.58 3535.01,4156.58 3539.25,4160.82 ccw(c3528.11,4171.96) 3539.25,4183.09 cw(c3550.41,4194.21) 3561.52,4205.36 3572.66,4194.23 3583.79,4183.09 ccw(c3594.91,4194.25) 3606.06,4205.36 3594.93,4216.5 3583.79,4227.63 cw(c3594.95,4238.75) 3606.06,4249.9 3617.2,4238.77 3628.33,4227.63 ccw(c3639.45,4238.79) 3650.6,4249.9 3639.47,4261.04 3628.33,4272.18 ; 3628.33,4272.17 cw(c3639.49,4283.29) 3650.61,4294.45 3661.74,4283.31 3672.88,4272.18 ccw(c3683.99,4283.33) 3695.15,4294.45 cw(c3706.28,4305.58) 3695.15,4316.72 v1(3700.01,4321.58)
U1_4: C7.1 U1.4 | length 165.6
  Top Layer w10.04: U1.4@3179.41,4966.08 3214.51,4966.08 3240.61,4990.98 C7.1
U3_8: R7.2 U3.8 | length 582
  Top Layer w10.04: v1(2350.01,3431.58) 2373.11,3431.58 R7.2 ; v1(2780.01,3486.58) 2790.01,3496.58 U3.8
  Bottom Layer w10.04: v1(2350.01,3431.58) 2405.01,3486.58 v1(2780.01,3486.58)
U3_9: R6.1 U3.9 | length 567.7
  Top Layer w10.04: v1(2350.01,3546.58) R6.1 ; v1(2780.01,3526.58) 2790.33,3516.26 U3.9
  Bottom Layer w10.04: v1(2350.01,3546.58) 2370.01,3526.58 v1(2780.01,3526.58)
U8_2: R31.2 U8.2 | length 105.6
  Top Layer w13.78: R31.2 2690.01,2546.58 2710.32,2566.89 U8.2
U8_4: R30.2 U8.4 | length 111.8
  Top Layer w13.78: U8.4 2749.7,2571.58 2785.01,2536.27 R30.2
USB_DN: U3.2 USB1.5 USB1.7 | length 627.3
  Top Layer w10.04: USB1.7 2490.01,3096.73 2490.01,3136.1 ; USB1.5 2519.53,3136.1 2565.01,3181.58 2565.01,3456.58 2624.69,3516.26 U3.2
USB_DP: U3.1 USB1.6 USB1.8 | length 775
  Top Layer w10.04: USB1.8@2440.51,3077.08 2395.61,3077.08 2395.21,3116.38 ; USB1.6 2395.18,3116.41 ; U3.1 2619.38,3535.95 2545.01,3461.58 2545.01,3366.58 2490.01,3311.58 2390.01,3311.58 2355.01,3276.58 2355.01,3156.58 2395.18,3116.41
VBAT_IN: C25.2 D6.1 Q1.2 R8.1 U8.10 | length 2962
  Top Layer w11.81: 2655.01,2865 2680,2865 2690.62,2854.38 U8.10
  Top Layer w19.68: R8.1 3530.63,3455.8 Q1.2
  Top Layer w23.62: C25.2 2580.01,2531.58 v1(2655.01,2606.58) ; v1(2655.01,2821.58) 2655.01,2896.58 2655.01,3116.58 2685.01,3146.58 D6.1 v1(2740,3146.58) ; v1(3035,2540) 3145,2540 ; v1(3425.01,3074.98) v1(3670,3075) ; R8.1 3532.61,3544.6 Q1.2 ; Q1.2 v1(3565,3453.82)
  Bottom Layer w23.62: v1(2655.01,2821.58) v1(2655.01,2606.58) 2968.42,2606.58 v1(3035,2540) ; v1(2740,3146.58) 2740.01,3139.98 2860.01,3019.98 3370.01,3019.98 v1(3425.01,3074.98) ; v1(3565,3453.82) 3565,3450 3655,3360 3655,3090 v1(3670,3075)
VBAT_OUT: C29.1 H1.4 Q1.3 R12.2 U4.1 U4.3 | length 2168.3
  Top Layer w23.62: Q1.3@3570.01,3359.38 3570.01,3376.58 3580.01,3386.58 3843.41,3386.58 3925.01,3304.98 3925.01,3241.58 ; 3855.01,3386.58 3855.01,3696.58 3870.01,3711.58 3985.01,3711.58 4035.01,3761.58 4035.01,3851.58 4000.61,3885.98 R12.2 ; H1.4 3985.01,2536.58 3985.01,3041.58 v1(4020.01,3076.58) ; v1(4020.01,3141.58) 4020.01,3171.58 4002.45,3189.14 U4.1 3927.45,3189.14 3925.01,3191.58 3925.01,3264.02 U4.3 4025.01,3264.02 4028.08,3260.95 C29.1@4100.01,3260.95
  Bottom Layer w23.62: v1(4020.01,3076.58) v1(4020.01,3141.58)
VCC_RTC: C26.2 C53.1 D1.2 U2.1 | length 1240.5
  Top Layer w10.04: C26.2 2921.58,3351.58 2975,3405 v1(2975,3770) ; v1(3070,3935) 3070.94,3935 U2.1
  Top Layer w23.62: C26.2 C53.1 2794.41,3242.18 2900.01,3136.58 2900.01,3031.58 2911.61,3019.98 D1.2
  Bottom Layer w10.04: v1(2975,3770) 2985,3770 3070,3855 v1(3070,3935)
pads on no net: CARD1. CARD1.1 CARD1.8 SW1. U1.7 U1.8 U2.2 U2.5 U2.6 U2.34 U2.37 U2.38 U2.45 U2.46 U3.4 U3.5 U3.6 U4.4 U5.10 U5.11 U8.5 U8.6 USB1.3 USB1.4 USB1.9 USB1.10

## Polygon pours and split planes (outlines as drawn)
GND on Bottom Layer (solid): 1710,5485 1805,5580 4805,5580 4685,5460 4685,1500 4435,1750 1500,1750
GND on Top Layer (solid): 1925,5585 2020,5680 5020,5680 4900,5560 4900,1600 4650,1850 1715,1850

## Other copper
Top Layer:
  rectangle net VBAT_IN: 3090,2485 3215,2605
  rectangle net GND: 3285,2485 3410,2605

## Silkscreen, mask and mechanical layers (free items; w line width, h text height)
Top Overlay:
  lines w10: 2315.01,3606.58 2795.01,3606.58 2795.01,3861.58 2315.01,3861.58 2315.01,3606.58 ; 2315.01,3866.58 2795.01,3866.58 2795.01,4076.58 2315.01,4076.58 2315.01,3866.58 ; 2905.01,4526.58 3715.01,4526.58 3715.01,5156.58 2905.01,5156.58 2905.01,4526.58 ; 3005,2380 3497.5,2380 3497.5,2715 3005,2715 3005,2380
  text "陀螺仪磁场计" at 3225.01,5066.58 h80
  text "可以不用焊接" at 3595.01,4551.58 h80 r90
  text "BOOT" at 2555.01,3911.58 h80
  text "RES" at 2565.01,3741.58 h80
  text "可以不用焊接" at 2315.01,3631.58 h80
  text "RX TX GND VCC" at 3520,2620.47 h59.05
  text "BATTEY" at 3035,2575 h80
  text "+  -" at 3109.43,2350.39 h80 r352
Bottom Overlay:
  lines w10: 2276.51,2461.58 4245.01,2461.58 ; 2276.51,2462.17 2276.51,5186.58 4245.01,5186.58 4245.01,2462.17 ; 2475.01,2462.29 2475.01,3131.58 2920.01,3131.58 2920.01,3301.58 3519.45,3301.58 3519.45,3131.58 4050.01,3131.58 4050.01,2462.29
  text "X-TRACK" at 3995.01,4588.47 h236.22
  text "2.8inch super" at 3957.76,4242.89 h157.48 r2
  text "1" at 3500.01,3034.08 h45
  text "18" at 2975.01,3029.08 h45
Top Solder:
  rectangle: 3090,2485 3215,2605
  rectangle: 3285,2485 3410,2605
Document:
  text "18*0.8mm" at 3390.01,3349.08 h45 r180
